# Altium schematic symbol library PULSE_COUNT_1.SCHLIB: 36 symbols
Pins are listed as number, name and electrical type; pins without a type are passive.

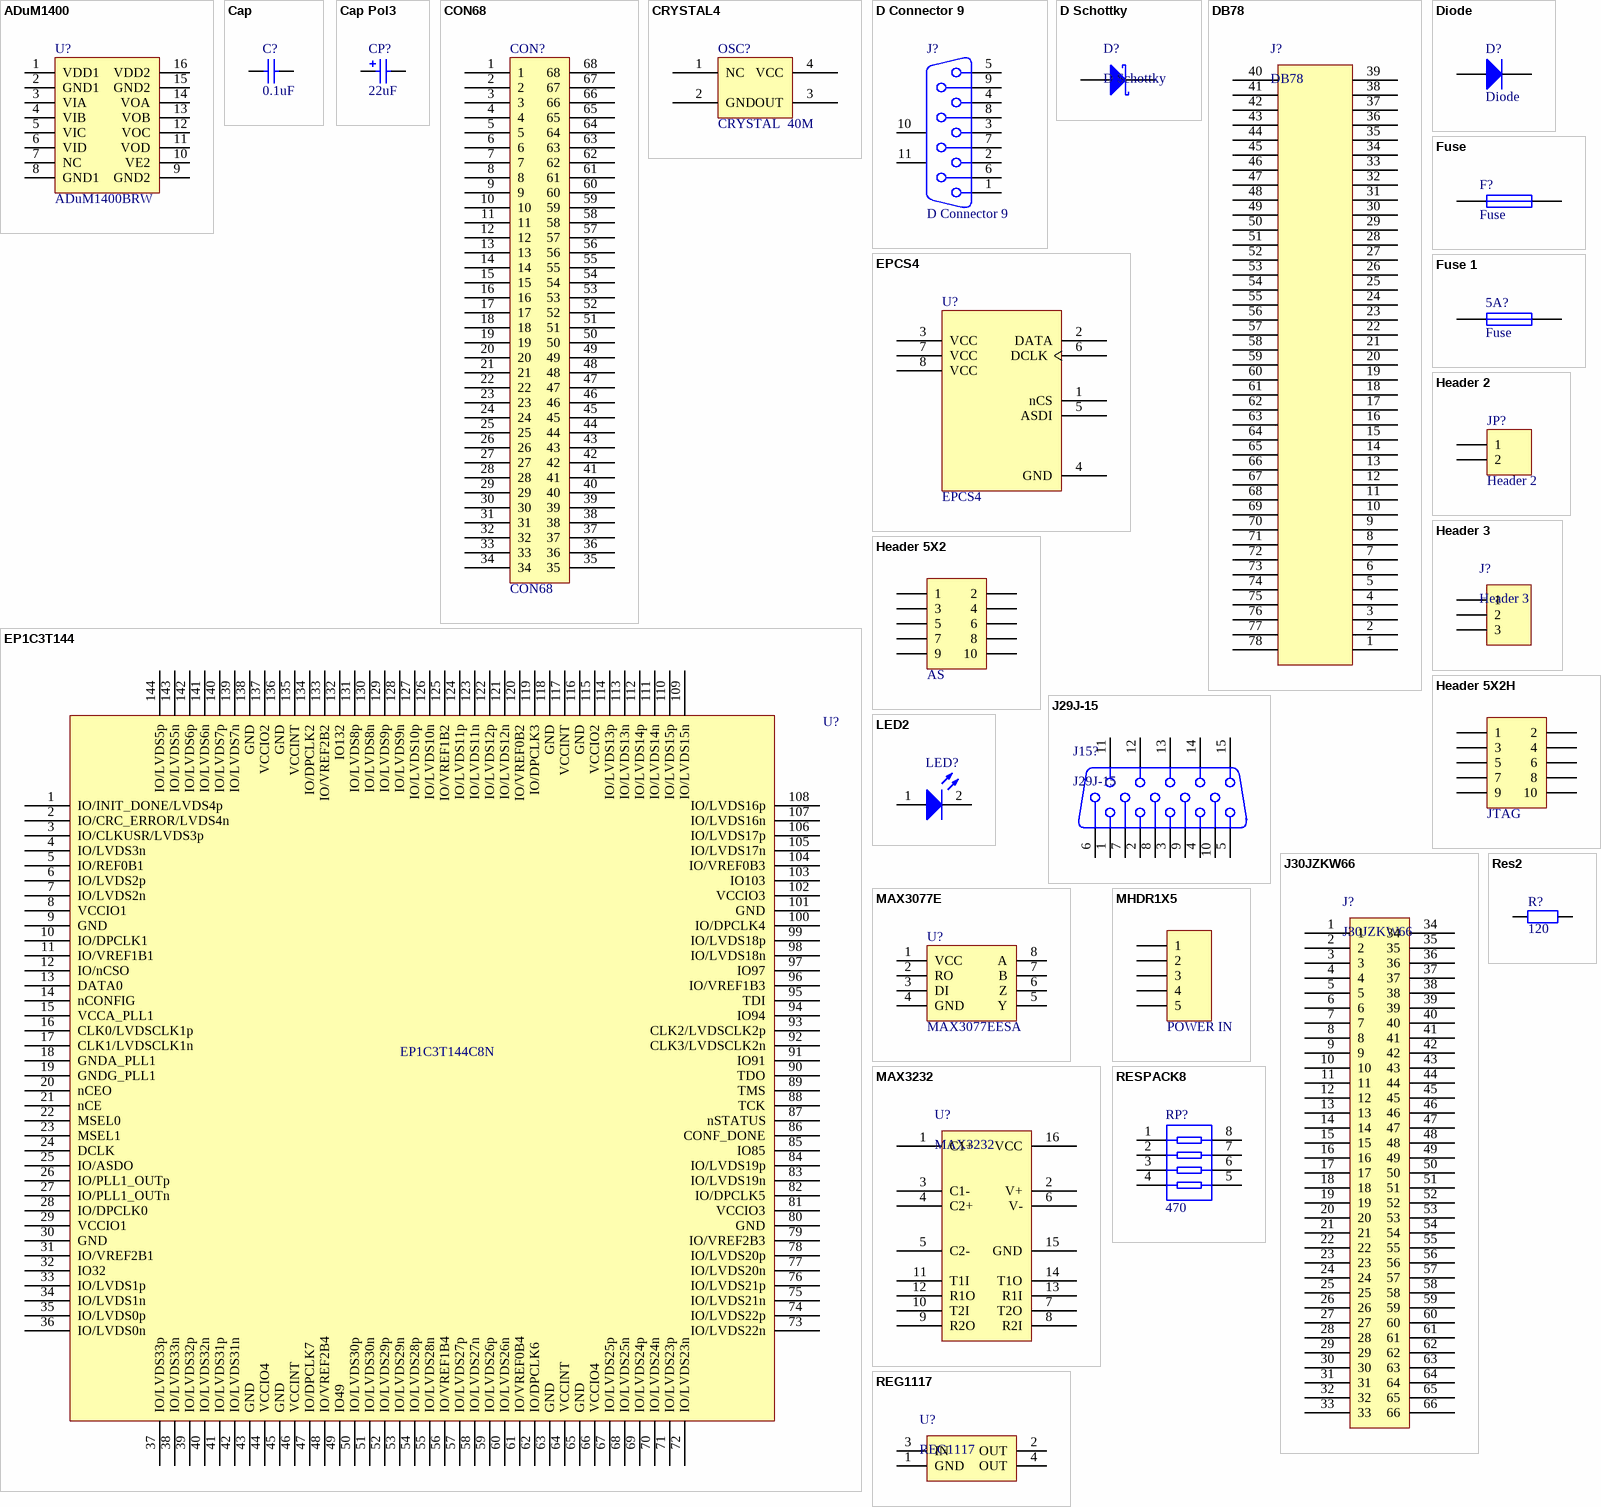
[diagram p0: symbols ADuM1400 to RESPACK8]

## ADuM1400
designator U?, comment ADuM1400BRW
footprint RW-16
pins: 1 VDD1, 2 GND1, 3 VIA, 4 VIB, 5 VIC, 6 VID, 7 NC, 8 GND1, 9 GND2, 10 VE2, 11 VOD, 12 VOC, 13 VOB, 14 VOA, 15 GND2, 16 VDD2

## Cap
designator C?, comment 0.1uF
Capacitor; Manufacturer: Generic Components; Value: 100pF; Class: Passive
simulation model CAP (Capacitor)
signal-integrity model Cap
footprint R2012-0805
pins: 1, 2

## Cap Pol3
designator CP?, comment 22uF
Polarized Capacitor (Surface Mount); Manufacturer: Generic Components; Class: Passive; Value: 10uF
footprint CC2012-0805
simulation model CAP (Capacitor)
signal-integrity model Cap Pol
footprint CC2012-1210
footprint C1210
pins: 1, 2

## CON68
designator CON?
footprint CHAMP-2H68
pins: 1, 2, 3, 4, 5, 6, 7, 8, 9, 10, 11, 12, 13, 14, 15, 16, 17, 18, 19, 20, 21, 22, 23, 24, 25, 26, 27, 28, 29, 30, 31, 32, 33, 34, 35, 36, 37, 38, 39, 40, 41, 42, 43, 44, 45, 46, 47, 48, 49, 50, 51, 52, 53, 54, 55, 56, 57, 58, 59, 60, 61, 62, 63, 64, 65, 66, 67, 68

## CRYSTAL4
designator OSC?, comment CRYSTAL  40M
footprint OSC
pins: 1 NC, 2 GND, 3 OUT, 4 VCC

## D Connector 9
designator J?
Receptacle Assembly, 9 Position, Right Angle; Package Information: Latest Revision: O; Positions: 9
footprint DSUB1.385-2H9 (Connector; D Subminiature; 9 Position; Right Angle; Pitch 1.385 mm)
signal-integrity model Connector
pins: 1, 2, 3, 4, 5, 6, 7, 8, 9, 10 MH1, 11 MH2

## D Schottky
designator D?
footprint SMB
pins: 1 A, 2 K

## DB78
designator J?
footprint DB78
pins: 1, 2, 3, 4, 5, 6, 7, 8, 9, 10, 11, 12, 13, 14, 15, 16, 17, 18, 19, 20, 21, 22, 23, 24, 25, 26, 27, 28, 29, 30, 31, 32, 33, 34, 35, 36, 37, 38, 39, 40, 41, 42, 43, 44, 45, 46, 47, 48, 49, 50, 51, 52, 53, 54, 55, 56, 57, 58, 59, 60, 61, 62, 63, 64, 65, 66, 67, 68, 69, 70, 71, 72, 73, 74, 75, 76, 77, 78

## Diode
designator D?
Default Diode; Manufacturer: Generic Components; Class: Discrete; SubClass: Diode - Switching
footprint DSO-C2/X3.3
simulation model DIODE (Diode)
signal-integrity model Diode
pins: 1 A, 2 K

## EP1C3T144
designator U?, comment EP1C3T144C8N
footprint TQFP144
pins: 1 IO/INIT_DONE/LVDS4p, 2 IO/CRC_ERROR/LVDS4n, 3 IO/CLKUSR/LVDS3p, 4 IO/LVDS3n, 5 IO/REF0B1, 6 IO/LVDS2p, 7 IO/LVDS2n, 8 VCCIO1, 9 GND, 10 IO/DPCLK1, 11 IO/VREF1B1, 12 IO/nCSO, 13 DATA0, 14 nCONFIG, 15 VCCA_PLL1, 16 CLK0/LVDSCLK1p, 17 CLK1/LVDSCLK1n, 18 GNDA_PLL1, 19 GNDG_PLL1, 20 nCEO, 21 nCE, 22 MSEL0, 23 MSEL1, 24 DCLK, 25 IO/ASDO, 26 IO/PLL1_OUTp, 27 IO/PLL1_OUTn, 28 IO/DPCLK0, 29 VCCIO1, 30 GND, 31 IO/VREF2B1, 32 IO32, 33 IO/LVDS1p, 34 IO/LVDS1n, 35 IO/LVDS0p, 36 IO/LVDS0n, 37 IO/LVDS33p, 38 IO/LVDS33n, 39 IO/LVDS32p, 40 IO/LVDS32n, 41 IO/LVDS31p, 42 IO/LVDS31n, 43 GND, 44 VCCIO4, 45 GND, 46 VCCINT, 47 IO/DPCLK7, 48 IO/VREF2B4, 49 IO49, 50 IO/LVDS30p, 51 IO/LVDS30n, 52 IO/LVDS29p, 53 IO/LVDS29n, 54 IO/LVDS28p, 55 IO/LVDS28n, 56 IO/VREF1B4, 57 IO/LVDS27p, 58 IO/LVDS27n, 59 IO/LVDS26p, 60 IO/LVDS26n, 61 IO/VREF0B4, 62 IO/DPCLK6, 63 GND, 64 VCCINT, 65 GND, 66 VCCIO4, 67 IO/LVDS25p, 68 IO/LVDS25n, 69 IO/LVDS24p, 70 IO/LVDS24n, 71 IO/LVDS23p, 72 IO/LVDS23n, 73 IO/LVDS22n, 74 IO/LVDS22p, 75 IO/LVDS21n, 76 IO/LVDS21p, 77 IO/LVDS20n, 78 IO/LVDS20p, 79 IO/VREF2B3, 80 GND, 81 VCCIO3, 82 IO/DPCLK5, 83 IO/LVDS19n, 84 IO/LVDS19p, 85 IO85, 86 CONF_DONE, 87 nSTATUS, 88 TCK, 89 TMS, 90 TDO, 91 IO91, 92 CLK3/LVDSCLK2n, 93 CLK2/LVDSCLK2p, 94 IO94, 95 TDI, 96 IO/VREF1B3, 97 IO97, 98 IO/LVDS18n, 99 IO/LVDS18p, 100 IO/DPCLK4, 101 GND, 102 VCCIO3, 103 IO103, 104 IO/VREF0B3, 105 IO/LVDS17n, 106 IO/LVDS17p, 107 IO/LVDS16n, 108 IO/LVDS16p, 109 IO/LVDS15n, 110 IO/LVDS15p, 111 IO/LVDS14n, 112 IO/LVDS14p, 113 IO/LVDS13n, 114 IO/LVDS13p, 115 VCCIO2, 116 GND, 117 VCCINT, 118 GND, 119 IO/DPCLK3, 120 IO/VREF0B2, 121 IO/LVDS12n, 122 IO/LVDS12p, 123 IO/LVDS11n, 124 IO/LVDS11p, 125 IO/VREF1B2, 126 IO/LVDS10n, 127 IO/LVDS10p, 128 IO/LVDS9n, 129 IO/LVDS9p, 130 IO/LVDS8n, 131 IO/LVDS8p, 132 IO132, 133 IO/VREF2B2, 134 IO/DPCLK2, 135 VCCINT, 136 GND, 137 VCCIO2, 138 GND, 139 IO/LVDS7n, 140 IO/LVDS7p, 141 IO/LVDS6n, 142 IO/LVDS6p, 143 IO/LVDS5n, 144 IO/LVDS5p

## EPCS4
designator U?
footprint SOIC8
pins: 1 nCS, 2 DATA, 3 VCC, 4 GND, 5 ASDI, 6 DCLK, 7 VCC, 8 VCC

## Fuse
designator F?
pins: 1, 2

## Fuse 1
designator 5A?, comment Fuse
footprint CC4532-1812
simulation model FUSE (Spice Subcircuit)
pins: 1, 2

## Header 2
designator JP?
Header, 2-Pin; Manufacturer: Generic Components; Class: Connector
footprint HDR1X2
signal-integrity model Connector
pins: 1, 2

## Header 3
designator J?
footprint POWER_CON
pins: 1, 2, 3

## Header 5X2
designator AS??, comment AS
Header, 5-Pin, Dual row; Manufacturer: Generic Components; Class: Connector
footprint FPGA_LOAD
signal-integrity model Connector
pins: 1, 2, 3, 4, 5, 6, 7, 8, 9, 10

## Header 5X2H
designator JTAG??, comment JTAG
Header, 5-Pin, Dual row,  Right Angle; Manufacturer: Generic Components; Class: Connector
footprint FPGA_LOAD
signal-integrity model Connector
pins: 1, 2, 3, 4, 5, 6, 7, 8, 9, 10

## J29J-15
designator J15?
footprint J29J-15
pins: 1, 2, 3, 4, 5, 6, 7, 8, 9, 10, 11, 12, 13, 14, 15

## J30JZKW66
designator J?
footprint J30J-66ZKW2
pins: 1, 2, 3, 4, 5, 6, 7, 8, 9, 10, 11, 12, 13, 14, 15, 16, 17, 18, 19, 20, 21, 22, 23, 24, 25, 26, 27, 28, 29, 30, 31, 32, 33, 34, 35, 36, 37, 38, 39, 40, 41, 42, 43, 44, 45, 46, 47, 48, 49, 50, 51, 52, 53, 54, 55, 56, 57, 58, 59, 60, 61, 62, 63, 64, 65, 66

## LED2
designator LED?, comment LED12V  (value not drawn)
Typical RED, GREEN, YELLOW, AMBER GaAs LED; Manufacturer: Generic Components; Class: Optoelectronic
footprint DSO-F2/D6.1
simulation model LED2 (Diode)
footprint 0805
footprint R2012-0805
pins: 1 A, 2 K

## MAX3077E
designator U?, comment MAX3077EESA
footprint DIP8
pins: 1 VCC, 2 RO, 3 DI, 4 GND, 5 Y, 6 Z, 7 B, 8 A

## MAX3232
designator U?
footprint SOJ-16_2
pins: 1 C1+, 2 V+, 3 C1-, 4 C2+, 5 C2-, 6 V-, 7 T2O, 8 R2I, 9 R2O, 10 T2I, 11 T1I, 12 R1O, 13 R1I, 14 T1O, 15 GND, 16 VCC

## MHDR1X5
designator POWER??, comment POWER IN
Header, 5-Pin; Manufacturer: Generic Components; Class: Connector
footprint CN5
signal-integrity model Connector
pins: 1, 2, 3, 4, 5

## REG1117
designator U?
footprint ZZ311
pins: 1 GND (power), 2 OUT (power), 3 IN (power), 4 OUT (power)

## Res2
designator R?, comment 120
Resistor
footprint R2012-0805
simulation model RESISTOR (Resistor)
signal-integrity model Res
pins: 1, 2
1 alternate drawing of the same symbol

## RESPACK8
designator RP?, comment 470
footprint RP8
pins: 1, 2, 3, 4, 5, 6, 7, 8

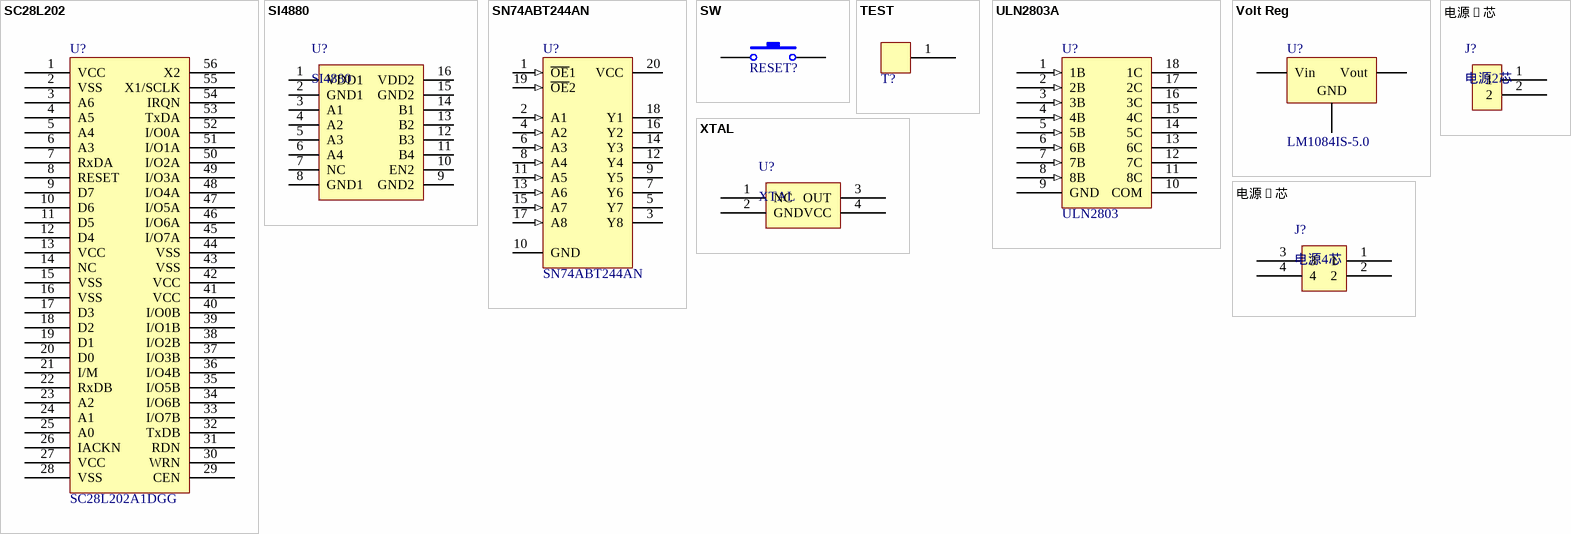
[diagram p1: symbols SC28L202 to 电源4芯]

## SC28L202
designator U?, comment SC28L202A1DGG
footprint TSSOP56
pins: 1 VCC, 2 VSS, 3 A6, 4 A5, 5 A4, 6 A3, 7 RxDA, 8 RESET, 9 D7, 10 D6, 11 D5, 12 D4, 13 VCC, 14 NC, 15 VSS, 16 VSS, 17 D3, 18 D2, 19 D1, 20 D0, 21 I/M, 22 RxDB, 23 A2, 24 A1, 25 A0, 26 IACKN, 27 VCC, 28 VSS, 29 CEN, 30 WRN, 31 RDN, 32 TxDB, 33 I/O7B, 34 I/O6B, 35 I/O5B, 36 I/O4B, 37 I/O3B, 38 I/O2B, 39 I/O1B, 40 I/O0B, 41 VCC, 42 VCC, 43 VSS, 44 VSS, 45 I/O7A, 46 I/O6A, 47 I/O5A, 48 I/O4A, 49 I/O3A, 50 I/O2A, 51 I/O1A, 52 I/O0A, 53 TxDA, 54 IRQN, 55 X1/SCLK, 56 X2

## SI4880
designator U?
footprint RW-16
pins: 1 VDD1, 2 GND1, 3 A1, 4 A2, 5 A3, 6 A4, 7 NC, 8 GND1, 9 GND2, 10 EN2, 11 B4, 12 B3, 13 B2, 14 B1, 15 GND2, 16 VDD2

## SN74ABT244AN
designator U?
Octal Buffer/Driver with 3-State Outputs; Package Information: Latest Revision: Oct-1995
footprint SN74ABT244ADW--SOIC20
signal-integrity model SN74ABT244AN
pins: 1 ~{OE}1 (in), 2 A1 (in), 3 Y8 (hiz), 4 A2 (in), 5 Y7 (hiz), 6 A3 (in), 7 Y6 (hiz), 8 A4 (in), 9 Y5 (hiz), 10 GND (power), 11 A5 (in), 12 Y4 (hiz), 13 A6 (in), 14 Y3 (hiz), 15 A7 (in), 16 Y2 (hiz), 17 A8 (in), 18 Y1 (hiz), 19 ~{OE}2 (in), 20 VCC (power)

## SW
designator RESET?  (value not drawn)
Switch; Manufacturer: Generic Components
footprint SW4
pins: 1, 2

## TEST
designator T?  (value not drawn)
footprint TEST
pins: 1

## ULN2803A
designator U?, comment ULN2803
Darlington transistor array
footprint ULN2803AFWG--SOIC18
pins: 1 1B (in), 2 2B (in), 3 3B (in), 4 4B (in), 5 5B (in), 6 6B (in), 7 7B (in), 8 8B (in), 9 GND (power), 10 COM (power), 11 8C (oc), 12 7C (oc), 13 6C (oc), 14 5C (oc), 15 4C (oc), 16 3C (oc), 17 2C (oc), 18 1C (oc)

## Volt Reg
designator U?, comment LM1084IS-5.0
Voltage Regulator; Manufacturer: Generic Components; Class: Power Management
footprint Lt1587 - duplicate
pins: 1 Vin, 2 GND, 3 Vout

## XTAL
designator U?
pins: 1 NC, 2 GND, 3 OUT, 4 VCC

## 电源2芯
designator J?
footprint 电源 2芯
pins: 1, 2

## 电源4芯
designator J?
footprint 电源4芯
pins: 1, 2, 3, 4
